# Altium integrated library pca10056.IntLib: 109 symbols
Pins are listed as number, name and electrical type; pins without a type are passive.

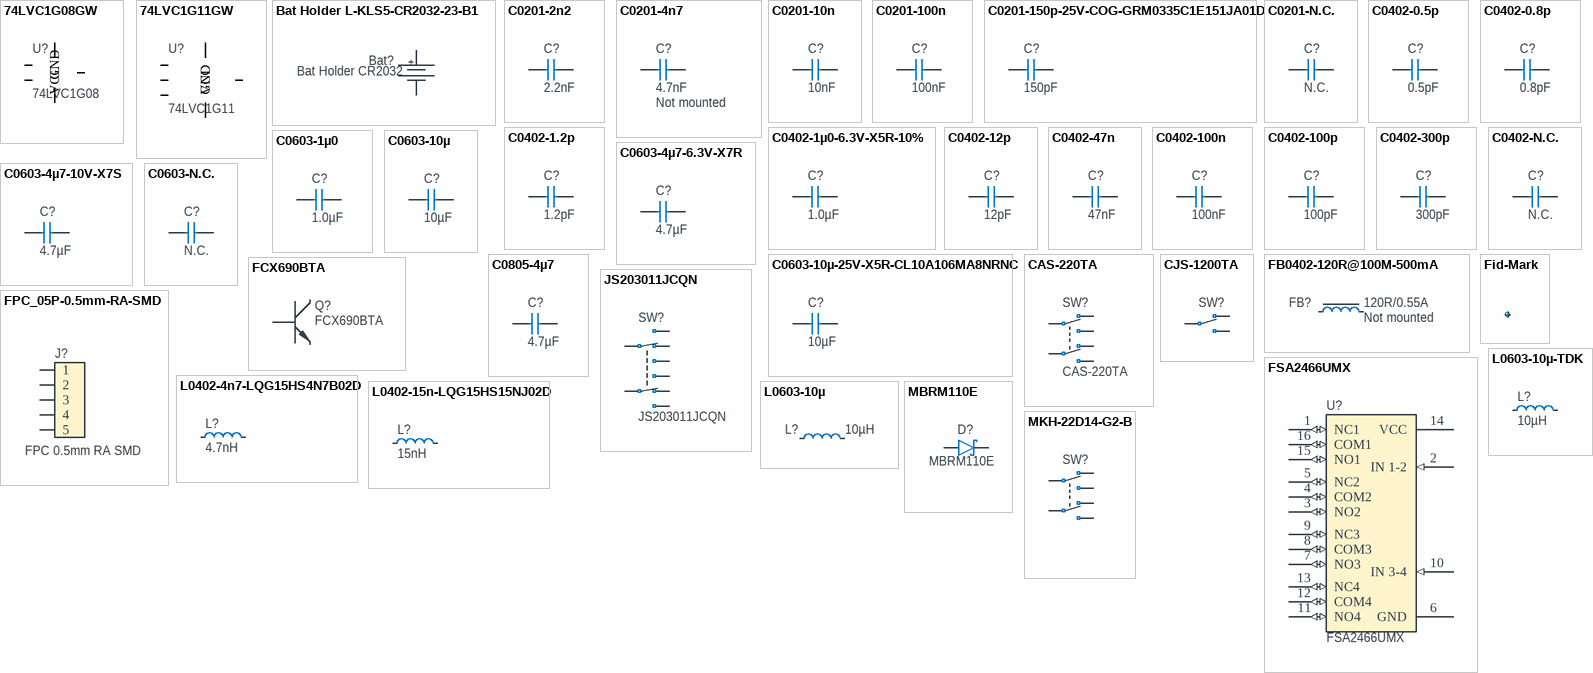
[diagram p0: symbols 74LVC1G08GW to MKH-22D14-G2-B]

## 74LVC1G08GW
designator U?, comment 74LVC1G08
Single 2-Input AND Gate; Part Number: 74LVC1G08GW; Manufacturer: NXP Semiconductors; Part number IPS: 00000009992; Part number Norautron: N.A.; Part number NEMS: 101900155; Artikkelnr Noca: 15049058; Pad Count: 5; Component Status: Active
footprint SOT65P210X100-5N
pins: 1 A, 2 B, 3 GND (power), 4 Y, 5 VCC (power)

## 74LVC1G11GW
designator U?, comment 74LVC1G11
Single 3-input AND gate; Part Number: 74LVC1G11GW; Manufacturer: NXP Semiconductors; Part number IPS: 00000001430; Part number Norautron: N.A.; Part number NEMS: 101900157; Artikkelnr Noca: 15079348; Pad Count: 6; Component Status: Active
footprint SOT65P210X100-6N
pins: 1 A, 2 GND (power), 3 B, 4 Y, 5 VCC (power), 6 C

## Bat Holder L-KLS5-CR2032-23-B1
designator Bat?, comment Bat Holder CR2032
Bat Holder CR2032 SMD; Part Number: Bat Holder L-KLS5-CR2032-23-B1; Manufacturer: KLS Electronic; Manufacturer Part Number: L-KLS5-CR2032-23-B1; Part number NEMS: 100500651; Artikkelnr Noca: N.A.; Pad Count: 2; Component Status: Active
footprint L-KLS5-CR2032-23-B1
pins: 1, 2

## C0201-2n2
designator C?, comment 2.2nF
Capacitor, X7R, ±10%, 10V; Part Number: C0201-2n2; Manufacturer: N.A.; Part number IPS: 00000001778; Part number Norautron: 26470002; Part number NEMS: 100200060; Pad Count: 2; Component Status: Active
footprint CAPC0603X03L_C
pins: 1, 2

## C0201-4n7
designator C?, comment 4.7nF  Assembly: Not mounted
Capacitor, X7R, ±10%, 10V; Part Number: C0201-4n7; Manufacturer: N.A.; Part number IPS: 00000001243; Part number NEMS: 100200063; Note: Chip Cap 1%; Pad Count: 2; Component Status: Active
footprint CAPC0603X03L_C
pins: 1, 2

## C0201-10n
designator C?, comment 10nF
Capacitor, X7R, ±10%; Part Number: C0201-10n; Manufacturer: N.A.; Part number IPS: 00000003480; Part number Norautron: 26621779; Part number NEMS: 100200067; Note: 10V; Pad Count: 2; Component Status: Active
footprint CAPC0603X03L_C
pins: 1, 2

## C0201-100n
designator C?, comment 100nF
Capacitor, X5R, ±10%; Part Number: C0201-100n; Manufacturer: N.A.; Part number IPS: 00000001248, 00000002505; Part number Norautron: 262071862; Part number NEMS: 100200078; Pad Count: 2; Note: 16V; Component Status: Active
footprint CAPC0603X03L_C
pins: 1, 2

## C0201-150p-25V-COG-GRM0335C1E151JA01D
designator C?, comment 150pF
Capacitor, Ceramic, NP0, ±5%, 25V; Part Number: C0201-150p-25V-COG-GRM0335C1E151JA01D; Manufacturer: N.A.; Part number IPS: 00000004306; Part number NEMS: 100200444; Note: Chip Cap 5%; Pad Count: 2; Component Status: Active
footprint CAPC0603X03L_C
pins: 1, 2

## C0201-N.C.
designator C?, comment N.C.
Not mounted; Part Number: C0201-N.C.; Manufacturer: N.A.; Part number NEMS: 100200001; Assembly: Not mounted; Note: Chip Cap; Pad Count: 2; Component Status: Active
footprint CAPC0603X03L_C_NC
pins: 1, 2

## C0402-0.5p
designator C?, comment 0.5pF
Capacitor, C0G, ±0.05pF, 50V; Part Number: C0402-0.5p; Manufacturer: Murata; Manufacturer Part Number: GJM1555C1HR50WB01; Part number IPS: 00000004293; Part number Norautron: N.A.; Part number NEMS: 100200112; Artikkelnr Noca: 20020007; Pad Count: 2; Component Status: Active
footprint CAPC1005X04L
pins: 1, 2

## C0402-0.8p
designator C?, comment 0.8pF
Capacitor, NP0, ±5%; Part Number: C0402-0.8p; Manufacturer: Murata; Manufacturer Part Number: GRM1555C1HR80WA01D; Part number IPS: 00000007782; Part number Norautron: N.A.; Part number NEMS: 100200116; Note: 50V; Artikkelnr Noca: 20029147; Pad Count: 2; Component Status: Active
footprint CAPC1005X04L
pins: 1, 2

## C0402-1.2p
designator C?, comment 1.2pF
Capacitor, NP0, ±0.1pF; Part Number: C0402-1.2p; Manufacturer: N.A.; Part number IPS: 00000005410; Part number NEMS: 100200119; Note: 50V; Artikkelnr Noca: 20029157; Pad Count: 2; Component Status: Active
footprint CAPC1005X04L
pins: 1, 2

## C0402-1µ0-6.3V-X5R-10%
designator C?, comment 1.0µF
Capacitor, X5R, ±10%, 6.3V; Part Number: C0402-1µ0-6.3V-X5R-10%; Manufacturer: N.A.; Part number Norautron: 26207137; Part number NEMS: 100200498; Pad Count: 2; Component Status: Active
footprint CAPC1005X04L
pins: 1, 2

## C0402-12p
designator C?, comment 12pF
Capacitor, NP0, ±2%; Part Number: C0402-12p; Manufacturer: N.A.; Part number IPS: 00000002398; Part number NEMS: 100200137; Note: 50V; Artikkelnr Noca: 20029159; Pad Count: 2; Component Status: Active
footprint CAPC1005X04L
pins: 1, 2

## C0402-47n
designator C?, comment 47nF
Capacitor, X7R, ±10%, 25V; Part Number: C0402-47n; Manufacturer: N.A.; Part number IPS: 00000003143; Part number NEMS: 100200180; Note: Chip Cap 10%; Artikkelnr Noca: 20039389; Pad Count: 2; Component Status: Active
footprint CAPC1005X04L
pins: 1, 2

## C0402-100n
designator C?, comment 100nF
Capacitor, X7R, ±10%; Part Number: C0402-100n; Manufacturer: N.A.; Part number IPS: 00000005296; Part number NEMS: 100200184; Note: 16V; Artikkelnr Noca: 20039200; Pad Count: 2; Component Status: Active
footprint CAPC1005X04L
pins: 1, 2

## C0402-100p
designator C?, comment 100pF
Capacitor, NP0, ±5%; Part Number: C0402-100p; Manufacturer: N.A.; Part number IPS: 00000002361; Part number NEMS: 100200148; Note: 50V; Artikkelnr Noca: 20029135; Pad Count: 2; Component Status: Active
footprint CAPC1005X04L
pins: 1, 2

## C0402-300p
designator C?, comment 300pF
Capacitor, C0G, ±5%, 50V; Part Number: C0402-300p; Manufacturer: N.A.; Part number IPS: 00000007788; Part number NEMS: 100200155; Artikkelnr Noca: 20020004; Pad Count: 2; Component Status: Active
footprint CAPC1005X04L
pins: 1, 2

## C0402-N.C.
designator C?, comment N.C.
Not mounted; Part Number: C0402-N.C.; Manufacturer: N.A.; Part number NEMS: 100200105; Note: Chip Cap; Assembly: Not mounted; Pad Count: 2; Component Status: Active
footprint CAPC1005X04L_NC
pins: 1, 2

## C0603-1µ0
designator C?, comment 1.0µF
Capacitor, X7R, ±10%; Part Number: C0603-1µ0; Manufacturer: N.A.; Part number IPS: 00000000616; Part number Norautron: 262083409; Part number NEMS: 100200271; Note: 16V; Artikkelnr Noca: 20039282; Pad Count: 2; Component Status: Active
footprint CAPC1608X06L
pins: 1, 2

## C0603-4µ7-6.3V-X7R
designator C?, comment 4.7µF
Capacitor, X7R, ±10%, 6.3V; Part Number: C0603-4µ7-6.3V-X7R; Manufacturer: Samsung Electro-Mechanics America; Manufacturer Part Number: CL10B475KQ8NQNC; Part number IPS: 00000002541; Part number Norautron: N.A.; Part number NEMS: 100200350; Artikkelnr Noca: 20039473; Pad Count: 2; Component Status: Active
footprint CAPC1608X06L
pins: 1, 2

## C0603-4µ7-10V-X7S
designator C?, comment 4.7µF
Capacitor, X7S, ±10%, 10V; Part Number: C0603-4µ7-10V-X7S; Manufacturer: N.A.; Part number IPS: 00000001779; Part number NEMS: 100200351; Artikkelnr Noca: 20030013; Pad Count: 2; Component Status: Active
footprint CAPC1608X06L
pins: 1, 2

## C0603-10µ
designator C?, comment 10µF
Capacitor, X5R, ±20%; Part Number: C0603-10µ; Manufacturer: N.A.; Part number IPS: 00000007785; Part number NEMS: 100200275; Note: 6.3V; Artikkelnr Noca: 20039234; Pad Count: 2; Component Status: Active
footprint CAPC1608X06L
pins: 1, 2

## C0603-10µ-25V-X5R-CL10A106MA8NRNC
designator C?, comment 10µF
Capacitor, X5R, ±20%, 25V; Part Number: C0603-10µ-25V-X5R-CL10A106MA8NRNC; Manufacturer: Samsung Electro-Mechanics America; Manufacturer Part Number: CL10A106MA8NRNC; Part number IPS: 00000009948; Part number Norautron: N.A.; Part number NEMS: 100200354; Artikkelnr Noca: 20039436; Pad Count: 2; Component Status: Active
footprint CAPC1608X06L
pins: 1, 2

## C0603-N.C.
designator C?, comment N.C.
Not mounted; Part Number: C0603-N.C.; Manufacturer: N.A.; Part number NEMS: 100200195; Pad Count: 2; Note: Chip Cap; Assembly: Not mounted; Component Status: Active
footprint CAPC1608X06L_NC
pins: 1, 2

## C0805-4µ7
designator C?, comment 4.7µF
Capacitor, X5R, ±10%, 16V; Part Number: C0805-4µ7; Manufacturer: N.A.; Part number IPS: 00000006289; Part number NEMS: 100200284; Artikkelnr Noca: 20039266; Pad Count: 2; Component Status: Active
footprint CAPC2012X11L
pins: 1, 2

## CAS-220TA
designator SW?
Slide Switch DPDT J Hook; Manufacturer: Copal Electronics Inc; Part number IPS: 00000009983; Part number NEMS: 101500003; Note: N.A.; Artikkelnr Noca: 50019042; Pad Count: 6; Component Status: Active
footprint CAS-220TA
pins: 1 N.O-1, 2 COM-1, 3 N.C-1, 4 N.O-2, 5 COM-2, 6 N.C-2

## CJS-1200TA
designator SW?, comment Switch  (value not drawn)
SMD slide Switch (ON-ON); Part Number: CJS-1200TA; Manufacturer: Copal Electronics Inc; Part number IPS: 00000009982; Part number Norautron: 26030738; Part number NEMS: 101500005; Note: N.A.; Artikkelnr Noca: 50019068; Pad Count: 3; Component Status: Active
footprint CJS-120xA
pins: 1 N.C, 2 COM, 3 N.O

## FB0402-120R@100M-500mA
designator FB?, comment 120R/0.55A  Assembly: Not mounted
Ferrite Bead, 120 Ohm @ 100MHz, 500mA, 250 mOhm Max; Part Number: FB0402-120R@100M-500mA; Manufacturer: Murata; Manufacturer Part Number: BLM15AG121SN1D; Part number IPS: 00000009954; Part number Norautron: 265230631; Part number NEMS: 100300099; Note: Chip EMIFIL Inductor Type Chip Ferrite Bead; Artikkelnr Noca: 33029317; Pad Count: 2; Component Status: Active
footprint INDC1005X04L
pins: 1, 2

## FCX690BTA
designator Q?
45V NPN high gain power transistor; Manufacturer: Diodes Incorporated; Part number IPS: 00000009974; Part number NEMS: 101300130; Note: N.A.; Artikkelnr Noca: 35010019; Pad Count: 3; Component Status: Active
footprint SOT89-150P409X160-3N
pins: 1 B, 2 C (power), 3 E (power)

## Fid-Mark
designator Fid?, comment Fiducial mark  (value not drawn)
Part Number: Fid-Mark; Manufacturer: N.A.; Part number NEMS: 100500073; Value: N.A.; Pad Count: 1; Component Status: Active
footprint Fiducial

## FPC_05P-0.5mm-RA-SMD
designator J?, comment FPC 0.5mm RA SMD
0.5mm FPC, 5P,Right Angle SMT,Double Contact,H=1.2mm,White, Tin plated; Part Number: FPC_05P-0.5mm-RA-SMD; Manufacturer: W-CON; Manufacturer Part Number: 5141-05RZDNWR02; Part number IPS: 00000007792; Part number Norautron: 26032377; Part number NEMS: 100500528; Note: N.A.; Artikkelnr Noca: 55010020; Pad Count: 7; Component Status: Active
footprint FPC_05P-0.5mm-RA-SMD
pins: 1, 2, 3, 4, 5

## FSA2466UMX
designator U?
Data / Audio Low-Voltage Dual DPDT Analog Switch; Manufacturer: ON Semiconductor; Part number IPS: 00000009986; Part number Norautron: 26500608; Part number NEMS: 101900422; Note: N.A.; Artikkelnr Noca: 15070069; Pad Count: 16; Component Status: Active
footprint XQFN40P180X260X50-16N
pins: 1 NC1 (io), 2 IN 1-2 (in), 3 NO2 (io), 4 COM2 (io), 5 NC2 (io), 6 GND (power), 7 NO3 (io), 8 COM3 (io), 9 NC3 (io), 10 IN 3-4 (in), 11 NO4 (io), 12 COM4 (io), 13 NC4 (io), 14 VCC (power), 15 NO1 (io), 16 COM1 (io)
1 alternate drawing of the same symbol

## JS203011JCQN
designator SW?
Slide Switch DP3T 300mA 6V; Manufacturer: C&K; Part number IPS: 00000004321; Part number NEMS: 101500099; Note: N.A.; Artikkelnr Noca: 50019116; Pad Count: 8; Component Status: Active
footprint Switch-Slide-J-Lead-DP3T-13x3.5mm
pins: 1 N.O, 2 N.C, 3 COM, 4 N.O, 5 N.O, 6 N.C, 7 COM, 8 N.O

## L0402-4n7-LQG15HS4N7B02D
designator L?, comment 4.7nH
Inductor, 700mA, ±0.1nH, 160mR LQG; Part Number: L0402-4n7-LQG15HS4N7B02D; Manufacturer: Murata; Manufacturer Part Number: LQG15HS4N7B02D; Part number NEMS: 100300410; Pad Count: 2; Note: High frequency chip inductor ±5%; Artikkelnr Noca: N.A.; Component Status: Active
footprint INDC1005X04L
pins: 1, 2

## L0402-15n-LQG15HS15NJ02D
designator L?, comment 15nH
Inductor, 450mA, ±5%,  0.32ohm; Part Number: L0402-15n-LQG15HS15NJ02D; Manufacturer: Murata; Manufacturer Part Number: LQG15HS15NJ02D; Part number NEMS: 100300412; Pad Count: 2; Note: High frequency chip inductor ±5%; Artikkelnr Noca: N.A.; Component Status: Active
footprint INDC1005X04L
pins: 1, 2

## L0603-10µ
designator L?, comment 10µH
Inductor, 80mA, ±10%; Part Number: L0603-10µ; Manufacturer: Taiyo Yuden; Manufacturer Part Number: LBMF1608T100K; Part number IPS: 00000007794; Part number Norautron: N.A.; Part number NEMS: 100300078; Note: LBMF1608T100K 10µH 80mA 0603; Artikkelnr Noca: 33029314; Pad Count: 2; Component Status: Active
footprint INDC1608X06L
pins: 1, 2

## L0603-10µ-TDK
designator L?, comment 10µH
Inductor, 250mA, ±20%, 1.05ohm. -55°C ~ 125°C; Part Number: L0603-10µ-TDK; Manufacturer: TDK Corporation; Manufacturer Part Number: MLZ1608M100WTD25; Part number Norautron: 26521771; Part number NEMS: 100300079; Note: N.A.; Pad Count: 2; Component Status: Active
footprint INDC1608X06L
pins: 1, 2

## MBRM110E
designator D?
Diode Schottky Vf=0.455V @ 100mA, Vr=10V, If=1000mA, Ir=1µA @ 10V; Manufacturer: ON Semiconductor; Manufacturer Part Number: MBRM110ET1G; Part number IPS: 00000009953; Part number NEMS: 101300099; Note: N.A.; Artikkelnr Noca: 10029172; Pad Count: 2; Component Status: Active
footprint DO-216AA
pins: 1 A, 3 C

## MKH-22D14-G2-B
designator SW?  (value not drawn)
Slide Switch DPDT; Manufacturer: Dailywell; Part number IPS: 00000004369; Part number NEMS: 101500096; Note: N.A.; Artikkelnr Noca: 50019112; Pad Count: 6; Component Status: Active
footprint MKH-22D14-G2-B
pins: 1 N.O-1, 2 COM-1, 3 N.C-1, 4 N.O-2, 5 COM-2, 6 N.C-2

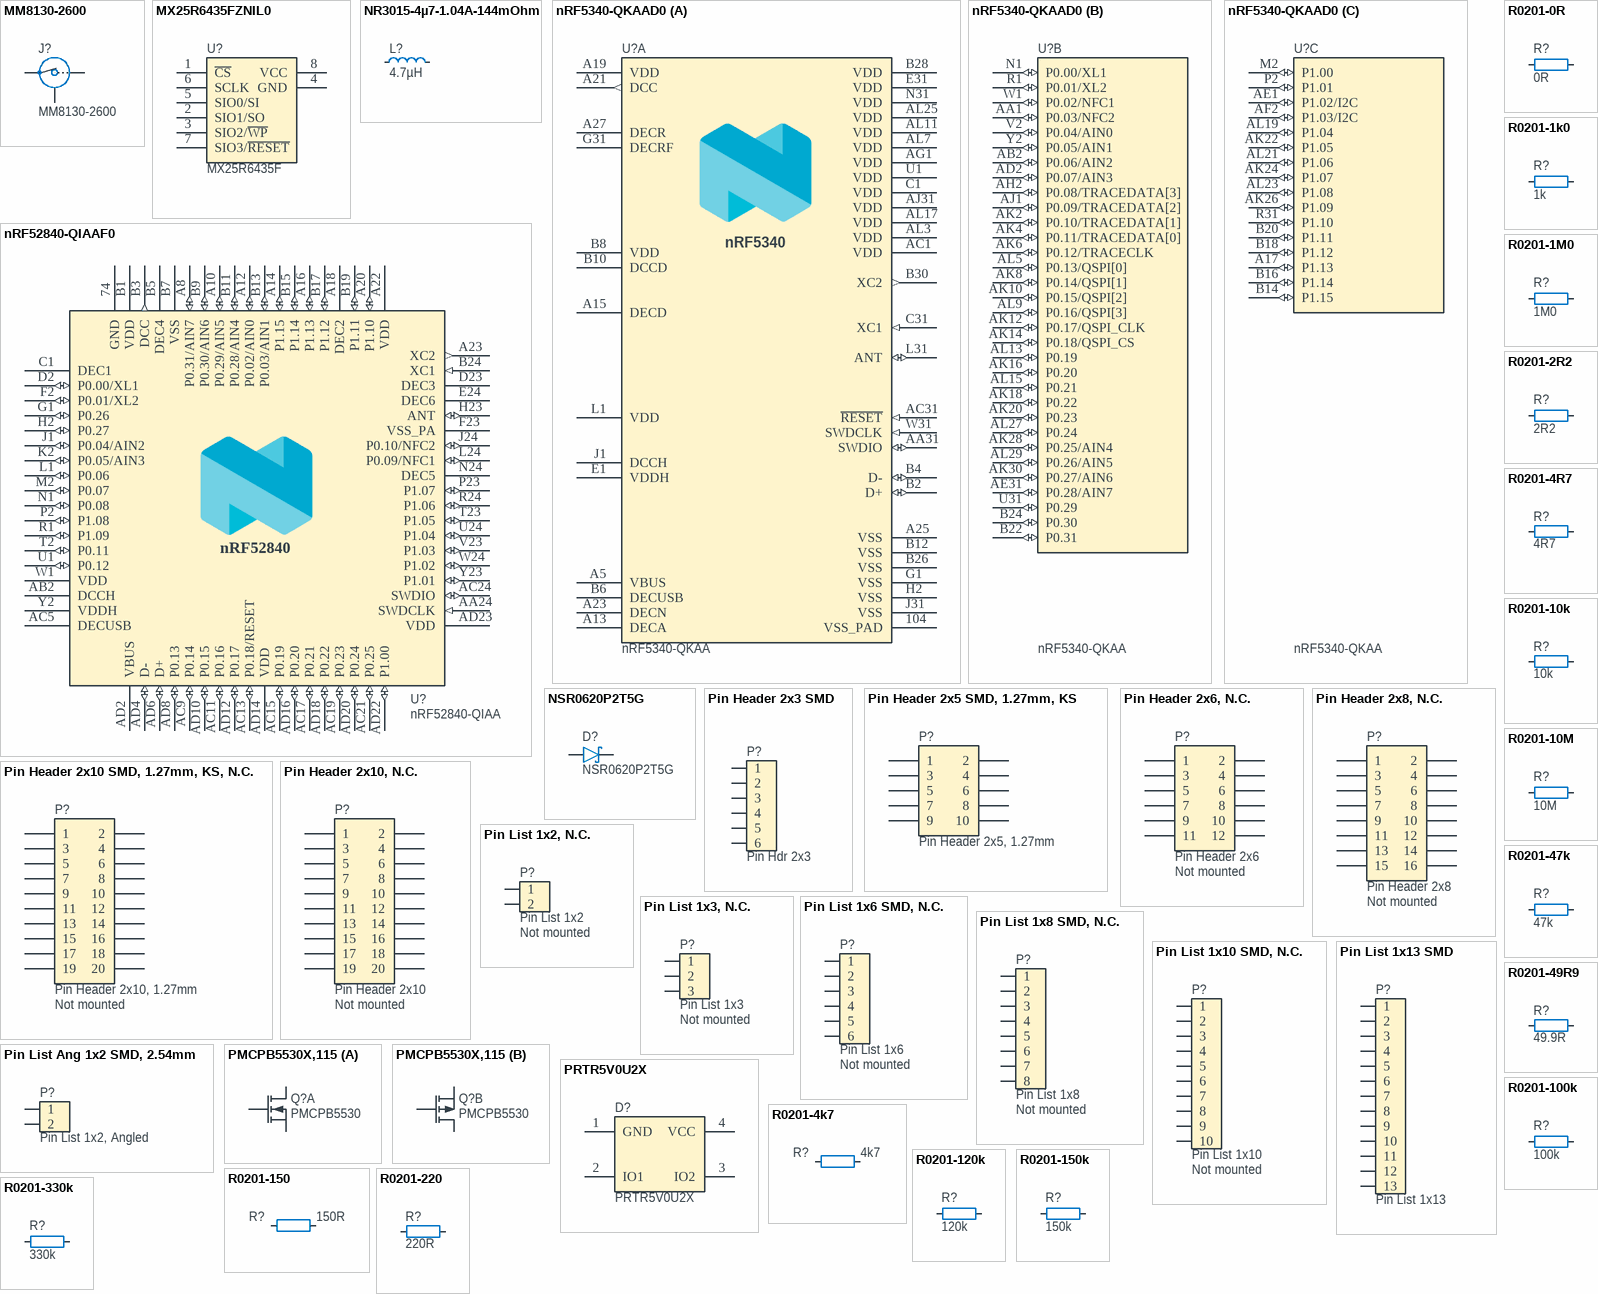
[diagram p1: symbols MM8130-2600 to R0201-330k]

## MM8130-2600
designator J?
Coaxial Connector with Switch; Manufacturer: Murata; Part number IPS: 00000009955; Part number Norautron: 26030338; Part number NEMS: 100500400; Note: N.A.; Artikkelnr Noca: 55029011; Pad Count: 3; Component Status: Active
footprint COAXIAL-SWF
pins: 1 IN, 2 Shield, 3 OUT

## MX25R6435FZNIL0
designator U?, comment MX25R6435F
Ultra low power, 64M-bit, serial multi I/O flash memory; Part Number: MX25R6435FZNIL0; Manufacturer: Macronix; Part number IPS: 00000004370; Part number NEMS: 101900438; Note: N.A.; Artikkelnr Noca: 15020015; Pad Count: 8; Component Status: Active
footprint SON127P600X80_HS-9N
pins: 1 ~{CS}, 2 SIO1/SO, 3 SIO2/~{WP}, 4 GND, 5 SIO0/SI, 6 SCLK, 7 SIO3/~{RESET}, 8 VCC, 9 GND hidden to GND

## NR3015-4µ7-1.04A-144mOhm
designator L?, comment 4.7µH
Ferrite Inductor, Shielded, 1,04A, 144mOhm; Part Number: NR3015-4µ7-1.04A-144mOhm; Manufacturer: Taiyo Yuden; Manufacturer Part Number: NR3015T4R7M; Part number IPS: 00000009960; Part number NEMS: 100300145; Note: N.A.; Artikkelnr Noca: 33029551; Pad Count: 2; Component Status: Active
footprint TY-NR3015
pins: 1, 2

## nRF5340-QKAAD0
designator U?, comment nRF5340-QKAA
Multi-protocol Bluetooth Low Energy, IEEE 802.15.4, ANT and 2.4GHz proprietary system-on-chip; Part Number: nRF5340-QKAAD0; Manufacturer: Nordic Semiconductor; Part number Norautron: NOD26470035; Part number NEMS: 102000216; Pad Count: 98; Note: N.A.; Component Status: Active
footprint AQFN40P700X700X85_HS-99N
part A pins: 104 VSS_PAD (power), A5 VBUS (power), A13 DECA (power), A15 DECD (power), A19 VDD (power), A21 DCC (out), A23 DECN (power), A25 VSS (power), A27 DECR (power), AA31 SWDIO (io), AC1 VDD (power), AC31 ~{RESET} (in), AG1 VDD (power), AG31 N.C. hidden, AJ31 VDD (power), AL3 VDD (power), AL7 VDD (power), AL11 VDD (power), AL17 VDD (power), AL25 VDD (power), B2 D+ (io), B4 D- (io), B6 DECUSB (power), B8 VDD (power), B10 DCCD (power), B12 VSS (power), B26 VSS (power), B28 VDD (power), B30 XC2 (out), C1 VDD (power), C31 XC1 (in), D2 N.C. hidden, E1 VDDH (power), E31 VDD (power), F2 N.C. hidden, G1 VSS (power), G31 DECRF (power), H2 VSS (power), J1 DCCH (power), J31 VSS (power), L1 VDD (power), L31 ANT (io), N31 VDD (power), T2 N.C. hidden, U1 VDD (power), W31 SWDCLK (in)
part B pins: AA1 P0.03/NFC2 (io), AB2 P0.06/AIN2 (io), AD2 P0.07/AIN3 (io), AE31 P0.28/AIN7 (io), AH2 P0.08/TRACEDATA[3] (io), AJ1 P0.09/TRACEDATA[2] (io), AK2 P0.10/TRACEDATA[1] (io), AK4 P0.11/TRACEDATA[0] (io), AK6 P0.12/TRACECLK (io), AK8 P0.14/QSPI[1] (io), AK10 P0.15/QSPI[2] (io), AK12 P0.17/QSPI_CLK (io), AK14 P0.18/QSPI_CS (io), AK16 P0.20 (io), AK18 P0.22 (io), AK20 P0.23 (io), AK28 P0.25/AIN4 (io), AK30 P0.27/AIN6 (io), AL5 P0.13/QSPI[0] (io), AL9 P0.16/QSPI[3] (io), AL13 P0.19 (io), AL15 P0.21 (io), AL27 P0.24 (io), AL29 P0.26/AIN5 (io), B22 P0.31 (io), B24 P0.30 (io), N1 P0.00/XL1 (io), R1 P0.01/XL2 (io), U31 P0.29 (io), V2 P0.04/AIN0 (io), W1 P0.02/NFC1 (io), Y2 P0.05/AIN1 (io)
part C pins: A17 P1.13 (io), AE1 P1.02/I2C (io), AF2 P1.03/I2C (io), AK22 P1.05 (io), AK24 P1.07 (io), AK26 P1.09 (io), AL19 P1.04 (io), AL21 P1.06 (io), AL23 P1.08 (io), B14 P1.15 (io), B16 P1.14 (io), B18 P1.12 (io), B20 P1.11 (io), M2 P1.00 (io), P2 P1.01 (io), R31 P1.10 (io)

## nRF52840-QIAAF0
designator U?, comment nRF52840-QIAA
Multi-protocol Bluetooth Low Energy, IEEE 802.15.4, ANT and 2.4GHz proprietary system-on-chip; Part Number: nRF52840-QIAAF0; Manufacturer: Nordic Semiconductor; Part number IPS: 80000002377; Part number NEMS: 102000222; Note: N.A.; Pad Count: 73; Component Status: Active
footprint AQFN50P700X700X85_HS-74N
pins: 74 GND (power), A8 P0.31/AIN7 (io), A10 P0.29/AIN5 (io), A12 P0.02/AIN0 (io), A14 P1.15 (io), A16 P1.13 (io), A18 DEC2 (power), A20 P1.10 (io), A22 VDD (power), A23 XC2 (out), AA24 SWDCLK (in), AB2 DCCH (power), AC5 DECUSB (power), AC9 P0.14 (io), AC11 P0.16 (io), AC13 P0.18/RESET (io), AC15 P0.19 (io), AC17 P0.21 (io), AC19 P0.23 (io), AC21 P0.25 (io), AC24 SWDIO (io), AD2 VBUS (power), AD4 D- (io), AD6 D+ (io), AD8 P0.13 (io), AD10 P0.15 (io), AD12 P0.17 (io), AD14 VDD (power), AD16 P0.20 (io), AD18 P0.22 (io), AD20 P0.24 (io), AD22 P1.00 (io), AD23 VDD (power), B1 VDD (power), B3 DCC (out), B5 DEC4 (power), B7 VSS (power), B9 P0.30/AIN6 (io), B11 P0.28/AIN4 (io), B13 P0.03/AIN1 (io), B15 P1.14 (io), B17 P1.12 (io), B19 P1.11 (io), B24 XC1 (in), C1 DEC1 (power), D2 P0.00/XL1 (io), D23 DEC3 (power), E24 DEC6 (power), F2 P0.01/XL2 (io), F23 VSS_PA (power), G1 P0.26 (io), H2 P0.27 (io), H23 ANT (io), J1 P0.04/AIN2 (io), J24 P0.10/NFC2 (io), K2 P0.05/AIN3 (io), L1 P0.06 (io), L24 P0.09/NFC1 (io), M2 P0.07 (io), N1 P0.08 (io), N24 DEC5 (power), P2 P1.08 (io), P23 P1.07 (io), R1 P1.09 (io), R24 P1.06 (io), T2 P0.11 (io), T23 P1.05 (io), U1 P0.12 (io), U24 P1.04 (io), V23 P1.03 (io), W1 VDD (power), W24 P1.02 (io), Y2 VDDH (power), Y23 P1.01 (io)

## NSR0620P2T5G
designator D?
20V schottky barrier diode, Vf 350 mV @ 100 mA, Ir 2.0 µA @ 10 V, If 500 mA; Manufacturer: ON Semiconductor; Part number IPS: 00000009952; Part number Norautron: 26311081; Part number NEMS: 101300131; Note: N.A.; Artikkelnr Noca: 10029169; Pad Count: 2; Component Status: Active
footprint SODFL100X40-2N
pins: 1 C, 2 A

## Pin Header 2x3 SMD
designator P?, comment Pin Hdr 2x3
Pin Header 2x3, 2.54mm (100mil) SMD; Part Number: Pin Header 2x3 SMD; Manufacturer: W-CON; Manufacturer Part Number: 1125-1203S0M116R1; Part number IPS: 00000009966; Part number Norautron: N.A.; Part number NEMS: 100500242; Artikkelnr Noca: 55010007; Pad Count: 6; Component Status: Active
footprint HDR_2x3-SMD
pins: 1, 2, 3, 4, 5, 6

## Pin Header 2x5 SMD, 1.27mm, KS
designator P?, comment Pin Header 2x5, 1.27mm
Pin Header 2x5, 1.27mm (50mil), SMD, Keying Shroud; Part Number: Pin Header 2x5 SMD, 1.27mm, KS; Manufacturer: W-CON; Manufacturer Part Number: 3132-10MS0BK00R1; Part number IPS: 00000009968; Part number NEMS: 100500261; Note: N.A.; Artikkelnr Noca: 55010009; Pad Count: 10; Component Status: Active
footprint HDR_2x5-SMD-1.27mm-K
pins: 1, 2, 3, 4, 5, 6, 7, 8, 9, 10

## Pin Header 2x6, N.C.
designator P?, comment Pin Header 2x6  Assembly: Not mounted
Pin Header 2x6, 2.54mm (100mil); Part Number: Pin Header 2x6, N.C.; Manufacturer: N.A.; Part number NEMS: 100500265; Pad Count: 12; Component Status: Active
footprint HDR_2x6-NC
pins: 1, 2, 3, 4, 5, 6, 7, 8, 9, 10, 11, 12

## Pin Header 2x8, N.C.
designator P?, comment Pin Header 2x8  Assembly: Not mounted
Pin Header 2x8, 2.54mm (100mil); Part Number: Pin Header 2x8, N.C.; Manufacturer: N.A.; Part number NEMS: 100500270; Pad Count: 16; Component Status: Active
footprint HDR_2x8-NC
pins: 1, 2, 3, 4, 5, 6, 7, 8, 9, 10, 11, 12, 13, 14, 15, 16
1 alternate drawing of the same symbol

## Pin Header 2x10 SMD, 1.27mm, KS, N.C.
designator P?, comment Pin Header 2x10, 1.27mm  Assembly: Not mounted
Pin Header 2x10, 1.27mm (50mil), SMD, Keying Shroud; Part Number: Pin Header 2x10 SMD, 1.27mm, KS, N.C.; Manufacturer: W-CON; Manufacturer Part Number: 3132-20MS0BK00R1; Part number NEMS: 100500279; Note: N.A.; Pad Count: 20; Component Status: Active
footprint HDR_2x10-SMD-1.27mm-NC
pins: 1, 2, 3, 4, 5, 6, 7, 8, 9, 10, 11, 12, 13, 14, 15, 16, 17, 18, 19, 20

## Pin Header 2x10, N.C.
designator P?, comment Pin Header 2x10  Assembly: Not mounted
Pin Header 2x10, 2.54mm (100mil); Part Number: Pin Header 2x10, N.C.; Manufacturer: N.A.; Part number NEMS: 100500274; Pad Count: 20; Component Status: Active
footprint HDR_2x10-NC
pins: 1, 2, 3, 4, 5, 6, 7, 8, 9, 10, 11, 12, 13, 14, 15, 16, 17, 18, 19, 20

## Pin List 1x2, N.C.
designator P?, comment Pin List 1x2  Assembly: Not mounted
Pin List 1x2, 2.54mm (100mil); Part Number: Pin List 1x2, N.C.; Manufacturer: N.A.; Part number NEMS: 100500298; Pad Count: 2; Component Status: Active
footprint LIST_1x2-NC
pins: 1, 2

## Pin List 1x3, N.C.
designator P?, comment Pin List 1x3  Assembly: Not mounted
Pin List 1x3, 2.54mm (100mil); Part Number: Pin List 1x3, N.C.; Manufacturer: N.A.; Part number NEMS: 100500305; Pad Count: 3; Component Status: Active
footprint LIST_1x3-NC
pins: 1, 2, 3

## Pin List 1x6 SMD, N.C.
designator P?, comment Pin List 1x6  Assembly: Not mounted
Pin List 1x6, 2.54mm (100mil), SMD; Part Number: Pin List 1x6 SMD, N.C.; Manufacturer: W-CON; Manufacturer Part Number: 1125-1106S0M116R2; Part number NEMS: 100500321; Note: N.A.; Artikkelnr Noca: 55010026; Pad Count: 6; Component Status: Active
footprint LIST_1x6_SMD-NC
pins: 1, 2, 3, 4, 5, 6

## Pin List 1x8 SMD, N.C.
designator P?, comment Pin List 1x8  Assembly: Not mounted
Pin List 1x8, 2.54mm (100mil), SMD; Part Number: Pin List 1x8 SMD, N.C.; Manufacturer: W-CON; Manufacturer Part Number: 1125-1108S0M116R2; Part number NEMS: 100500330; Note: N.A.; Artikkelnr Noca: 55010006; Pad Count: 8; Component Status: Active
footprint LIST_1x8_SMD-NC
pins: 1, 2, 3, 4, 5, 6, 7, 8

## Pin List 1x10 SMD, N.C.
designator P?, comment Pin List 1x10  Assembly: Not mounted
Pin List 1x10, 2.54mm (100mil), SMD; Part Number: Pin List 1x10 SMD, N.C.; Manufacturer: W-CON; Manufacturer Part Number: 1125-1110S0M116R2; Part number NEMS: 100500338; Note: N.A.; Artikkelnr Noca: 55010028; Pad Count: 10; Component Status: Active
footprint LIST_1x10_SMD-NC
pins: 1, 2, 3, 4, 5, 6, 7, 8, 9, 10

## Pin List 1x13 SMD
designator P?, comment Pin List 1x13
Pin List 1x13, 2.54mm (100mil), SMD; Part Number: Pin List 1x13 SMD; Manufacturer: N.A.; Part number IPS: 00000002499; Part number NEMS: 100500345; Pad Count: 13; Component Status: Active
footprint LIST_1x13_SMD
pins: 1, 2, 3, 4, 5, 6, 7, 8, 9, 10, 11, 12, 13

## Pin List Ang 1x2 SMD, 2.54mm
designator P?, comment Pin List 1x2, Angled
Pin List 1x2, 2.54mm (100mil), Right Angled, SMD; Part Number: Pin List Ang 1x2 SMD, 2.54mm; Manufacturer: W-CON; Manufacturer Part Number: 1125B-1102S0Z135R2; Part number IPS: 00000009972; Part number NEMS: 100500354; Note: N.A.; Artikkelnr Noca: 55010023; Pad Count: 2; Component Status: Active
footprint LIST_ANG_1x2-SMD-2.54MM
pins: 1, 2

## PMCPB5530X,115
designator Q?, comment PMCPB5530
Mosfet Array N and P-Channel 20V 4A (Ta), 3.4A (Ta) 490mW Surface Mount 6-HUSON-EP (2x2); Part Number: PMCPB5530X,115; Manufacturer: Nexperia; Part number IPS: 00000001918; Part number NEMS: 101300165; Note: N.A.; Pad Count: 8; Component Status: Active
footprint PMCPB5530X
part A pins: 1 S1, 2 G1, 6 D1
part B pins: 3 D2, 4 S2, 5 G2

## PRTR5V0U2X
designator D?
Ultra low capacitance double rail-to-rail ESD protection diode; Manufacturer: NXP Semiconductors; Part number IPS: 00000009951; Part number Norautron: 26313940; Part number NEMS: 101300082; Note: N.A.; Artikkelnr Noca: 10069015; Pad Count: 4; Component Status: Active
footprint SOT190P230X110-4L
pins: 1 GND, 2 IO1, 3 IO2, 4 VCC

## R0201-0R
designator R?, comment 0R
Resistor, ±5%, 0.05W; Part Number: R0201-0R; Manufacturer: N.A.; Part number IPS: 00000003245; Part number NEMS: 100100001; Note: Chip Res 5%; Pad Count: 2; Component Status: Active
footprint RESC0603X03L_C
pins: 1, 2

## R0201-1k0
designator R?, comment 1k
Resistor, ±1%, 0.05W; Part Number: R0201-1k0; Manufacturer: N.A.; Part number IPS: 00000005786; Part number NEMS: 100100043; Note: Chip Res 1%; Pad Count: 2; Component Status: Active
footprint RESC0603X03L_C
pins: 1, 2

## R0201-1M0
designator R?, comment 1M0
Resistor, ±1%, 0.05W; Part Number: R0201-1M0; Manufacturer: N.A.; Part number IPS: 00000001418; Part number Norautron: 26107108; Part number NEMS: 100100093; Note: Chip Res 1%; Pad Count: 2; Component Status: Active
footprint RESC0603X03L_C
pins: 1, 2

## R0201-2R2
designator R?, comment 2R2
Resistor, ±1%, 0.05W; Part Number: R0201-2R2; Manufacturer: N.A.; Part number Norautron: 26470029; Part number NEMS: 100100006; Pad Count: 2; Note: Chip Res 1%; Component Status: Active
footprint RESC0603X03L_C
pins: 1, 2

## R0201-4k7
designator R?, comment 4k7
Resistor, ±1%, 0.05W; Part Number: R0201-4k7; Manufacturer: N.A.; Part number IPS: 00000001706; Part number NEMS: 100100061; Note: Chip Res 1%; Pad Count: 2; Component Status: Active
footprint RESC0603X03L_C
pins: 1, 2

## R0201-4R7
designator R?, comment 4R7
Resistor, ±1%, 0.05W; Part Number: R0201-4R7; Manufacturer: N.A.; Part number IPS: 00000002486; Part number NEMS: 100100010; Note: Chip Res 1%; Pad Count: 2; Component Status: Active
footprint RESC0603X03L_C
pins: 1, 2

## R0201-10k
designator R?, comment 10k
Resistor, ±1%, 0.05W; Part Number: R0201-10k; Manufacturer: N.A.; Part number IPS: 00000001255; Part number Norautron: 26107101; Part number NEMS: 100100065; Note: Chip Res 1%; Pad Count: 2; Component Status: Active
footprint RESC0603X03L_C
pins: 1, 2

## R0201-10M
designator R?, comment 10M
Resistor, ±1%, 0.05W; Part Number: R0201-10M; Manufacturer: N.A.; Part number IPS: 00000001426; Part number NEMS: 100100105; Note: Chip Res 1%; Pad Count: 2; Component Status: Active
footprint RESC0603X03L_C
pins: 1, 2

## R0201-47k
designator R?, comment 47k
Resistor, ±1%, 0.05W; Part Number: R0201-47k; Manufacturer: N.A.; Part number IPS: 00000001423; Part number NEMS: 100100076; Note: Chip Res 1%; Pad Count: 2; Component Status: Active
footprint RESC0603X03L_C
pins: 1, 2

## R0201-49R9
designator R?, comment 49.9R
Resistor, ±1%, 0.05W; Part Number: R0201-49R9; Manufacturer: N.A.; Part number Norautron: 26107071; Part number NEMS: 100100612; Pad Count: 2; Note: Chip Res 1%; Component Status: Active
footprint RESC0603X03L_C
pins: 1, 2

## R0201-100k
designator R?, comment 100k
Resistor, ±1%, 0.05W; Part Number: R0201-100k; Manufacturer: N.A.; Part number IPS: 00000001419; Part number Norautron: 26108487; Part number NEMS: 100100080; Note: Chip Res 1%; Pad Count: 2; Component Status: Active
footprint RESC0603X03L_C
pins: 1, 2

## R0201-120k
designator R?, comment 120k
Resistor, ±1%, 0.05W; Part Number: R0201-120k; Manufacturer: N.A.; Part number IPS: 00000001425; Part number NEMS: 100100081; Note: Chip Res 1%; Pad Count: 2; Component Status: Active
footprint RESC0603X03L_C
pins: 1, 2

## R0201-150
designator R?, comment 150R
Resistor, ±1%, 0.05W; Part Number: R0201-150; Manufacturer: N.A.; Part number IPS: 00000001420; Part number NEMS: 100100029; Note: Chip Res 1%; Pad Count: 2; Component Status: Active
footprint RESC0603X03L_C
pins: 1, 2

## R0201-150k
designator R?, comment 150k
Resistor, ±1%, 0.05W; Part Number: R0201-150k; Manufacturer: N.A.; Part number IPS: 00000001422; Part number NEMS: 100100082; Note: Chip Res 1%; Pad Count: 2; Component Status: Active
footprint RESC0603X03L_C
pins: 1, 2

## R0201-220
designator R?, comment 220R
Resistor, ±1%, 0.05W; Part Number: R0201-220; Manufacturer: N.A.; Part number IPS: 00000000863; Part number Norautron: 26107014; Part number NEMS: 100100032; Note: Chip Res 1%; Pad Count: 2; Component Status: Active
footprint RESC0603X03L_C
pins: 1, 2

## R0201-330k
designator R?, comment 330k
Resistor, ±1%, 0.05W; Part Number: R0201-330k; Manufacturer: N.A.; Part number IPS: 00000001424; Part number NEMS: 100100087; Note: Chip Res 1%; Pad Count: 2; Component Status: Active
footprint RESC0603X03L_C
pins: 1, 2

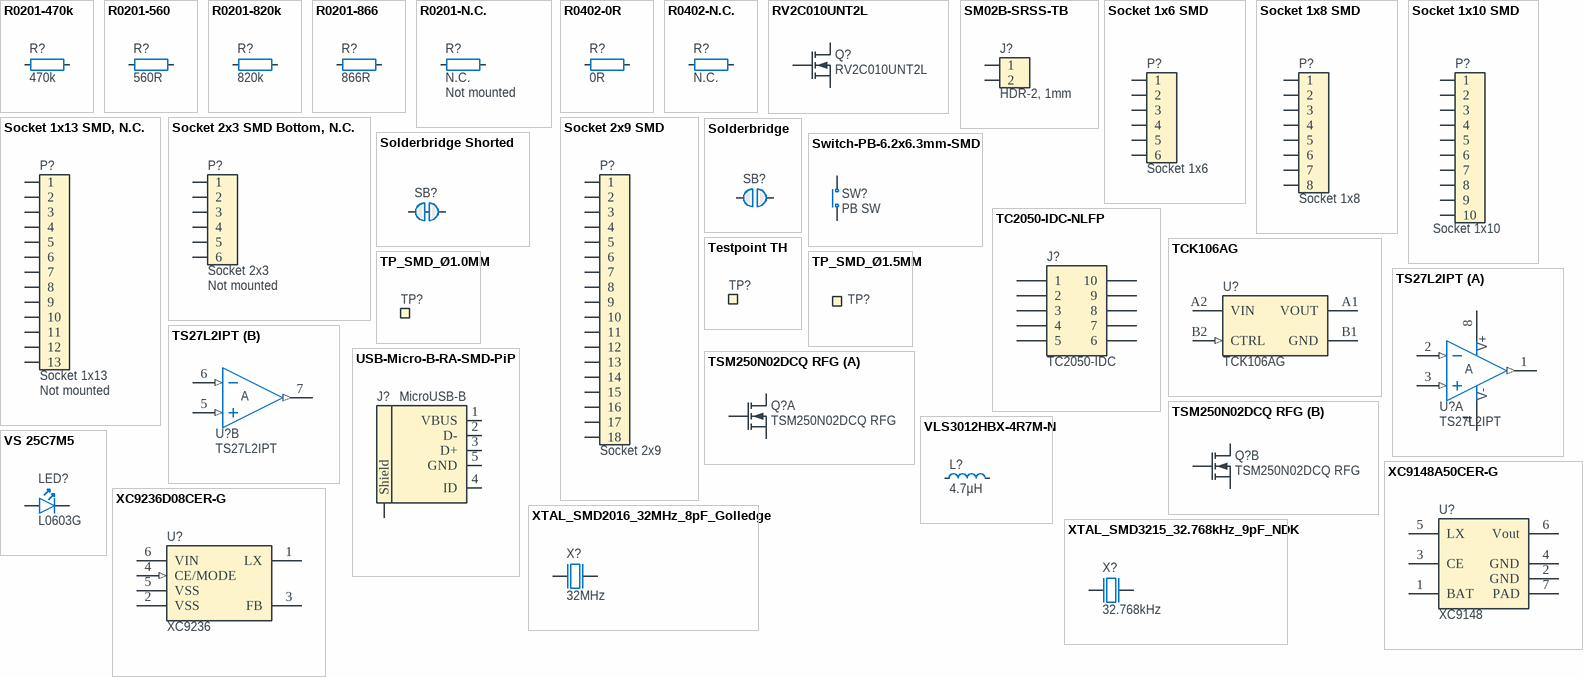
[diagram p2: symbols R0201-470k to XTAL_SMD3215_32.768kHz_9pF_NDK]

## R0201-470k
designator R?, comment 470k
Resistor, ±1%, 0.05W; Part Number: R0201-470k; Manufacturer: N.A.; Part number IPS: 00000001428; Part number NEMS: 100100089; Note: Chip Res 1%; Pad Count: 2; Component Status: Active
footprint RESC0603X03L_C
pins: 1, 2

## R0201-560
designator R?, comment 560R
Resistor, ±1%, 0.05W; Part Number: R0201-560; Manufacturer: N.A.; Part number NEMS: 100100038; Note: Chip Res 1%; Pad Count: 2; Component Status: Active
footprint RESC0603X03L_C
pins: 1, 2

## R0201-820k
designator R?, comment 820k
Resistor, ±1%, 0.05W; Part Number: R0201-820k; Manufacturer: N.A.; Part number IPS: 00000001427; Part number NEMS: 100100092; Note: Chip Res 1%; Pad Count: 2; Component Status: Active
footprint RESC0603X03L_C
pins: 1, 2

## R0201-866
designator R?, comment 866R
Resistor, ±1%, 0.05W; Part Number: R0201-866; Manufacturer: N.A.; Part number IPS: 00000004368; Part number NEMS: 100100042; Note: Chip Res 1%; Pad Count: 2; Component Status: Active
footprint RESC0603X03L_C
pins: 1, 2

## R0201-N.C.
designator R?, comment N.C.  Assembly: Not mounted
Not mounted; Part Number: R0201-N.C.; Manufacturer: N.A.; Part number NEMS: 100100107; Note: Chip Res; Pad Count: 2; Component Status: Active
footprint RESC0603X03L_C_NC
pins: 1, 2

## R0402-0R
designator R?, comment 0R
Resistor, ±5%, 0.063W; Part Number: R0402-0R; Manufacturer: N.A.; Part number IPS: 00000007128; Part number NEMS: 100100109; Note: Chip Res 5%; Artikkelnr Noca: 27049000; Pad Count: 2; Component Status: Active
footprint RESC1005X04L
pins: 1, 2

## R0402-N.C.
designator R?, comment N.C.
Not mounted; Part Number: R0402-N.C.; Manufacturer: N.A.; Part number NEMS: 100100281; Note: Chip Res; Assembly: Not mounted; Pad Count: 2; Component Status: Active
footprint RESC1005X04L_NC
pins: 1, 2

## RV2C010UNT2L
designator Q?
N-Channel MOSFET, 20V, 1A, 470mOhm, 400mW; Manufacturer: Rohm Semiconductor; Part number IPS: 00000009976; Part number Norautron: 26320026; Part number NEMS: 101300132; Note: N.A.; Artikkelnr Noca: 35010020; Pad Count: 3; Component Status: Active
footprint DFN65P100X40-3L
pins: 1 G, 2 S, 3 D

## SM02B-SRSS-TB
designator J?, comment HDR-2, 1mm
1.0mm pitch connector side entry SMD; Part Number: SM02B-SRSS-TB; Manufacturer: JST Sales America Inc.; Manufacturer Part Number: SM02B-SRSS-TB(LF)(SN); Part number IPS: 00000007791; Part number Norautron: N.A.; Part number NEMS: 100500383; Note: JST, Header; Artikkelnr Noca: 55010030; Pad Count: 2; Component Status: Active
footprint SM02B-SRSS-TB
pins: 1, 2

## Socket 1x6 SMD
designator P?, comment Socket 1x6
Socket 1x6, 2.54mm (100mil), SMD; Part Number: Socket 1x6 SMD; Manufacturer: W-CON; Manufacturer Part Number: 2171-106MS0CUNR1; Part number IPS: 00000009964; Part number Norautron: 26032370; Part number NEMS: 100500408; Note: N.A.; Artikkelnr Noca: 55030001; Pad Count: 6; Component Status: Active
footprint SOCKET_1x6_SMD
pins: 1, 2, 3, 4, 5, 6

## Socket 1x8 SMD
designator P?, comment Socket 1x8
Socket 1x8, 2.54mm (100mil), SMD; Part Number: Socket 1x8 SMD; Manufacturer: W-CON; Manufacturer Part Number: 2171-108MS0CUNR1; Part number IPS: 00000009963; Part number Norautron: 26032369; Part number NEMS: 100500412; Note: N.A.; Artikkelnr Noca: 55030002; Pad Count: 8; Component Status: Active
footprint SOCKET_1x8_SMD
pins: 1, 2, 3, 4, 5, 6, 7, 8

## Socket 1x10 SMD
designator P?, comment Socket 1x10
Socket 1x10, 2.54mm (100mil), SMD; Part Number: Socket 1x10 SMD; Manufacturer: W-CON; Manufacturer Part Number: 2171-110MS0CUNR1; Part number IPS: 00000009965; Part number Norautron: 26032371; Part number NEMS: 100500416; Note: N.A.; Artikkelnr Noca: 55030004; Pad Count: 10; Component Status: Active
footprint SOCKET_1x10_SMD
pins: 1, 2, 3, 4, 5, 6, 7, 8, 9, 10

## Socket 1x13 SMD, N.C.
designator P?, comment Socket 1x13  Assembly: Not mounted
Socket 1x13, 2.54mm (100mil), SMD; Part Number: Socket 1x13 SMD, N.C.; Manufacturer: W-CON; Manufacturer Part Number: 2171-113MS0CUNR1; Part number NEMS: 100500422; Note: N.A.; Pad Count: 13; Component Status: Active
footprint LIST_1x13_SMD-NC
pins: 1, 2, 3, 4, 5, 6, 7, 8, 9, 10, 11, 12, 13

## Socket 2x3 SMD Bottom, N.C.
designator P?, comment Socket 2x3  Assembly: Not mounted
Socket 2x3, 2.54mm (100mil), SMD; Part Number: Socket 2x3 SMD Bottom, N.C.; Manufacturer: W-CON; Manufacturer Part Number: 2171-203MS0CUNR1; Part number NEMS: 100500434; Note: N.A.; Artikkelnr Noca: 55030010; Pad Count: 6; Component Status: Active
footprint SOCKET_2x3_SMD-2.54mm-bottom-NC
pins: 1, 2, 3, 4, 5, 6

## Socket 2x9 SMD
designator P?, comment Socket 2x9
Socket 2x9, 2.54mm (100mil), SMD; Part Number: Socket 2x9 SMD; Manufacturer: W-CON; Manufacturer Part Number: 2171-209MS0CUNR1; Part number IPS: 00000004367; Part number NEMS: 100500440; Note: N.A.; Artikkelnr Noca: 55030011; Pad Count: 18; Component Status: Active
footprint SOCKET_2x9_SMD-2.54mm
pins: 1, 2, 3, 4, 5, 6, 7, 8, 9, 10, 11, 12, 13, 14, 15, 16, 17, 18

## Solderbridge
designator SB?  (value not drawn)  (no BOM)
Manufacturer: N.A.; Part number NEMS: 100500458; Pad Count: 2; Component Status: Active
footprint Solderbridge
pins: 1 0, 2 1

## Solderbridge Shorted
designator SB?, comment Solderbridge  (value not drawn)  (net tie, no BOM)
Shorted Solderbridge; Part Number: Solderbridge Shorted; Manufacturer: N.A.; Part number NEMS: 100500459; Pad Count: 2; Component Status: Active
footprint Solderbridge_Shorted
pins: 1 0, 2 1

## Switch-PB-6.2x6.3mm-SMD
designator SW?, comment PB SW
Tactile Switch, SPNO, SMD, 160gf, 6.2x6.3x2.5mm; Part Number: Switch-PB-6.2x6.3mm-SMD; Manufacturer: Dailywell; Manufacturer Part Number: TS604VM1-025BR-R; Part number IPS: 00000007812; Part number NEMS: 101500001; Note: N.A.; Artikkelnr Noca: 50019106; Pad Count: 4; Component Status: Active
footprint Switch-PB-6.2x6.3mm-SMD
pins: 1 N.O, 2 COM

## TC2050-IDC-NLFP
designator J?, comment TC2050-IDC  (no BOM)
CBL PLUG-OF-NAILS 10-PIN; Part Number: TC2050-IDC-NLFP; Manufacturer: Tag-Connect LLC; Part number NEMS: 100500463; Artikkelnr Noca: N.A.; Pad Count: 10; Component Status: Active
footprint TC2050-IDC-NLFP
pins: 1, 2, 3, 4, 5, 6, 7, 8, 9, 10

## TCK106AG
designator U?
1.0 A Load Switch IC with Slew Rate Control Driver in Ultra Small Package; Manufacturer: Toshiba; Manufacturer Part Number: TCK106AG,LF; Part number IPS: 00000004390; Part number Norautron: 26500627; Part number NEMS: 101900575; Note: N.A.; Pad Count: 4; Component Status: Active
footprint BGA4C40P2X2_76X76X62
pins: A1 VOUT (power), A2 VIN (power), B1 GND (power), B2 CTRL (in)

## Testpoint TH
designator TP?, comment TP  (value not drawn)  (no BOM)
Testpoint, through hole; Part Number: Testpoint TH; Manufacturer: N.A.; Part number NEMS: 100500464; Pad Count: 1; Component Status: Active
footprint TESTPAD-TH
pins: 1

## TP_SMD_Ø1.0MM
designator TP?, comment Ø1.0mm,SMD  (value not drawn)  (no BOM)
1.0mm circular SMD testpad; Part Number: TP_SMD_Ø1.0MM; Manufacturer: Nordic Semiconductor; Manufacturer Part Number: N.A.; Part number NEMS: 100500475; Pad Count: 1; Component Status: Active
footprint TP_SMD_D1.0mm
pins: 1

## TP_SMD_Ø1.5MM
designator TP?, comment Ø1.5mm,SMD  (value not drawn)  (no BOM)
1.5mm circular SMD testpad; Part Number: TP_SMD_Ø1.5MM; Manufacturer: Nordic Semiconductor; Manufacturer Part Number: N.A.; Part number NEMS: 100500477; Pad Count: 1; Component Status: Active
footprint TP_SMD_D1.5mm
pins: 1

## TS27L2IPT
designator U?
Precision very low power CMOS dual operational amplifier; Manufacturer: STMicroelectronics; Part number IPS: 00000009991; Part number NEMS: 101900442; Note: N.A.; Artikkelnr Noca: 17010019; Pad Count: 8; Component Status: Active
footprint TSOP65P640X120-8N
part A pins: 1 OUT1 (out), 2 IN1- (in), 3 IN1+ (in), 4 V- (power), 8 V+ (power)
part B pins: 5 IN2+ (in), 6 IN2- (in), 7 OUT2 (out)

## TSM250N02DCQ RFG
designator Q?
Dual N Ch MOFET, 5.8A, 55mOhm max, 620mW; Manufacturer: Taiwan Semiconductor; Part number IPS: 00000001703; Part number NEMS: 101300161; Note: N.A.; Pad Count: 6; Component Status: Active
footprint DFN65P200X200X80_HS-6N
part A pins: 1 S1, 2 G1, 6 D1
part B pins: 3 D2, 4 S2, 5 G2

## USB-Micro-B-RA-SMD-PiP
designator J?, comment MicroUSB-B
MicroUSB-B-SMT; Part Number: USB-Micro-B-RA-SMD-PiP; Manufacturer: Allen Creations Corp.; Manufacturer Part Number: AJU55-BS2111-L; Part number IPS: 00000007790; Part number NEMS: 100500490; Note: N.A.; Artikkelnr Noca: 55029020; Pad Count: 5; Component Status: Active
footprint USB-Micro-B-RA-SMD-PiP
pins: 1 VBUS (power), 2 D-, 3 D+, 4 ID, 5 GND (power), 6 Shield (power)

## VLS3012HBX-4R7M-N
designator L?, comment 4.7µH
4.7µH Shielded Wirewound Inductor 2.23A 201 mOhm Max Nonstandard; Part Number: VLS3012HBX-4R7M-N; Manufacturer: TDK Corporation; Part number NEMS: 100300407; Pad Count: 2; Note: N.A.; Component Status: Active
footprint VLS3012HBX
pins: 1, 2

## VS 25C7M5
designator LED?, comment L0603G
LED, Green, 0603, 573nm, Vf=2.0V, 24mcd, - 40 to +85°C; Part Number: VS 25C7M5; Manufacturer: Victory Electronics; Part number IPS: 00000001274, 00000009961; Part number Norautron: 26313411; Part number NEMS: 101400097; Note: N.A.; Artikkelnr Noca: 13019193; Pad Count: 2; Component Status: Active
footprint LED_0603_G
pins: 1 C, 2 A

## XC9148A50CER-G
designator U?, comment XC9148
1.4A Driver Transistor Built-In, Multi Functional Step-Up DC/DC Converter; Part Number: XC9148A50CER-G; Manufacturer: Torex Semiconductor; Part number NEMS: 101900670; Pad Count: 6; Note: N.A.; Component Status: Active
footprint USP-6C
pins: 1 BAT (power) "Power Input", 2 GND (power) "Ground", 3 CE "Chip Enable", 4 GND (power) "Ground", 5 LX "Switching", 6 Vout (oe) "Output Voltage", 7 PAD (power) "Ground"

## XC9236D08CER-G
designator U?, comment XC9236
600mA Driver Transistor Built-In, Synchronous Step-Down DC/DC Converters; Part Number: XC9236D08CER-G; Manufacturer: Torex Semiconductor; Part number IPS: 00000004325; Part number NEMS: 101900207; Note: N.A.; Artikkelnr Noca: 17030085; Pad Count: 6; Component Status: Active
footprint USP-6C
pins: 1 LX, 2 VSS (power), 3 FB (power), 4 CE/MODE (in), 5 VSS (power), 6 VIN (power), 7 VSS (power) hidden to GND

## XTAL_SMD2016_32MHz_8pF_Golledge
designator X?, comment 32MHz
XTAL SMD 2016, 32MHz, Cl=8pF, Tol: ±10ppm, Stab: ±15ppm; Part Number: XTAL_SMD2016_32MHz_8pF_Golledge; Manufacturer: Golledge; Manufacturer Part Number: MP06003; Part number IPS: 00000001431; Part number Norautron: N.A.; Part number NEMS: 101600041; Note: XTAL SMD 32.000MHz; Artikkelnr Noca: 22010050; Pad Count: 4; Component Status: Active
footprint BT-XTAL_2016
pins: 1 inp, 2 GND hidden to GND, 3 out, 4 GND hidden to GND

## XTAL_SMD3215_32.768kHz_9pF_NDK
designator X?, comment 32.768kHz
XTAL SMD 3215, 32.768kHz, 9pF, ±20ppm; Part Number: XTAL_SMD3215_32.768kHz_9pF_NDK; Manufacturer: NDK; Manufacturer Part Number: NX3215SA-32.768K-STD-MUA-9; Part number IPS: 00000005419; Part number Norautron: N.A.; Part number NEMS: 101600019; Note: XTAL SMD 32.768kHz; Artikkelnr Noca: 22010049; Pad Count: 2; Component Status: Active
footprint XTAL_3215
pins: 1 inp, 2 out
